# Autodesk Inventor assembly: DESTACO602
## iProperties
Title: DESTACO602
Author: GJOHNST2
Shininess: 20.0
Length Units: 11272
Angle Units: 11286
Time Units: 11279
Mass Units: 11290
Length Display Precision: 3
Angle Display Precision: 0
Compacted: True
PropertySet Name: _Private Model Information
Created: 2001-11
Part Number: DESTACO602
Description: MODEL 602
Document SubType Name: Assembly
Designer: GJOHNST2
Control State: 0
Master: False
Checked Out: False
PropertySet Name: Design Tracking Control
Density: 0.0
Volumn: 0.0
Area: 0.0
PropertySet Name: Model Information
